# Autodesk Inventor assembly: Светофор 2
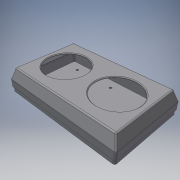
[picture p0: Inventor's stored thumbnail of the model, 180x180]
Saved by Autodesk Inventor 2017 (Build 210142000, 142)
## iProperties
Part Number: Светофор 2
Material: Типовые
Document SubType Name: Assembly
Designer: Система Знаний
Author: Система Знаний
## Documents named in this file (3)
- C:\Users\Система Знаний\Documents\Светофор 2.iam
- C:\Users\Система Знаний\Documents\Коробка светофора (2).ipt
- C:\Users\Система Знаний\Documents\Крышка светофора 2.ipt
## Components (2 placed, 2 different names)
1. Коробка светофора (2):1 — Совмещение:1, Совмещение:2, Заподлицо:1
2. Крышка светофора 2:1 — Совмещение:1, Совмещение:2, Заподлицо:1
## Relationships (3: Mate 2, Flush 1)
- Совмещение:1 [Mate]: Коробка светофора (2):1 ↔ Крышка светофора 2:1
- Совмещение:2 [Mate]: Коробка светофора (2):1 ↔ Крышка светофора 2:1
- Заподлицо:1 [Flush]: Коробка светофора (2):1 ↔ Крышка светофора 2:1
